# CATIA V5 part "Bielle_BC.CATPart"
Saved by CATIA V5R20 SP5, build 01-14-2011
Part number: Bielle BC
Publications: "Corps principal"
Bounding box of the stored display mesh (mm): x 3 to 12, y -1.883 to 47.029, z 5.773 to 16.018
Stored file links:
  C:\Documents and Settings\pschann\Bureau\IAO\Bielle_BC.CATPart
  C:\Documents and Settings\pschann\Bureau\IAO\Bielle_AB.CATPart
  C:\Documents and Settings\pschann\Bureau\IAO\pschann.CATProduct
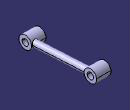
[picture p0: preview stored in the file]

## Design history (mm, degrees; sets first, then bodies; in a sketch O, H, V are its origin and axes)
External parameters (linked from other documents)
  `External.Longueur axe pivot` = 6 mm
  `External.Diamètre pivot` = 4 mm
  `External.Epaisseur pivot` = 2 mm
  `External.Diamètre bielle` = 4 mm
Set1
  Plane1: type Offset, RefPlane yz-plane, Offset 3 {= `External.Longueur axe pivot` /2}
  Sketch1 on Plane1, origin (3, 0, 0), H (0, 1, 0), V (0, 0, 1)
    circle A1 centre (2.1167, 9.7734) radius 4
    reference projected point E1 (2.1167, 9.7734) from Point1
    radius A1 = 4 {= `External.Diamètre pivot` /2+`External.Epaisseur pivot`}
    concentricity: A1 E1
Set2
  Point1 "B": linked copy from another document
  Line1: linked copy from another document
  Point2 "C": linked copy from another document
Body1 (main body)
  Pad1: profile Sketch1, direction (1, 0, 0), length 9 {= `External.Longueur axe pivot` *1.5}
  Plane2: type Normal, Curve Line1, RefPoint Point1
  Sketch2 on Plane2, origin (0, 2.622, 0.6561), H (1, 0, 0), V (0, -0.0553, 0.9985)
    circle A1 centre (9.6, 9.1313) radius 2
    point P1 (9.6, 9.1313)
    reference projected line E1 through (0, 9.1313) direction (1, 0) from axis of face of Pad1 from Sketch1.A1
    reference projected line E2 (12, 14.0732) -> (12, 6.0732) from edge [face of Pad1 from Sketch1.A1 | end face of Pad1]
    radius A1 = 2 {= `External.Diamètre bielle` /2}
    distance P1 E2 = 2.4 {= `External.Longueur axe pivot` /2.5}
    coincidence: P1 E1
  Plane3: type Normal, Curve Line1, RefPoint Point2
  Pad2: profile Sketch2, direction (0, -0.9985, -0.0553), up to Plane3
  Sketch3 on end face of Pad1, origin (12, 0, 0), H (0, 1, 0), V (0, 0, 1)
    circle A1 centre (2.1167, 9.7734) radius 2
    reference projected circle E1 centre (2.1167, 9.7734) radius 4 from edge [face of Pad1 from Sketch1.A1 | end face of Pad1]
    radius A1 = 2 {= `External.Diamètre pivot` /2}
    concentricity: A1 E1
  Pocket1: profile Sketch3, direction (-1, 0, 0), up to start face of Pad1
  Point3: type Between, FirstPoint Point1, SecondPoint Point2, Ratio 0.5, Support Line1
  Plane4: type Normal, Curve Line1, RefPoint Point3
  Mirror1: of Pad1, Sketch1, Pocket1, about Plane4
